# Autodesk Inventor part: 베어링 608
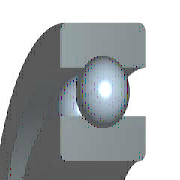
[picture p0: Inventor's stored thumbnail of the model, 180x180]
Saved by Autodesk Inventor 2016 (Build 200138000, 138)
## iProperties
IsCustomPart: 1
Created: 2012-02
Part Number: 베어링 608
Material: 강철, 연강
Description: 깊은 그루브 볼 베어링
Document SubType Name: Modeling
Standard: KS B 2023
Designer: mduedu
Standards Organization: KS
Language: ko-KR
Size Designation: 608 - 8 x 22 x 7
Categories: <MemberInstance><Categories><Category DisplayName="샤프트 부품" InternalName="7f7aeb1f-a693-4053-b835-cee3144e0d98" Mnemonic="SHFT"><Category DisplayName="베어링" Inter
Density: 1 g/cm^3
Appearance: 노란색
Author: mduedu
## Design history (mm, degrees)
sketch "스케치" dims "d0" = 3.64 (= -0.26 x WD + 0.26 x BD)
  geometry: L1 (1.68, 7.5)-(5.32, 7.5); L2 (3.5, 7.5)-(3.5, 5.68); L3 (3.5, 7.5)-(3.5, 9.32); L4 (2.148, 6.282)-(0, 6.282); L5 (0, 4)-(7, 4); L6 (2.148, 8.718)-(0, 8.718); L7 (0, 11)-(7, 11); L8 (7, 4)-(7, 6.282); L9 (4.852, 6.282)-(7, 6.282); L10 (4.852, 8.718)-(7, 8.718); L11 (7, 11)-(7, 8.718); L12 (-1.4, 0)-(8.4, 0) reference; L13 (0, -0.3)-(0, 5.3) reference
  constraints: 22 end point, 4 point on line, 2 collinear, 2 perpendicular, 2 symmetric about line, 1 midpoint, 1 parallel, 14 other
  dimensions: "d9" = 8 diameter of L5 L12 (= WD); "d11" = 22 diameter of L7 L12 (= BD); "d12" = 7 distance between parallel lines of L8 L13 (= KB); "d13" = 12.564 diameter of L9 L12 (= 0.326 x BD + 0.674 x WD)
revolve "본체" stored, may be unused: angle "d6" = 90 deg
revolve "볼" stored, may be unused: angle "d7" = 90 deg
pattern_circular "IDS_ARRAYBALL[SIMPL:T]" dims angle "d3" = 360 deg
body "Solid1"
fillet "모깎기1" dims "d1" = 0.3 (= KRS)
other parameters: "WD" = 8 [user parameter; used in 5 equation terms], "BD" = 22 [user parameter; used in 5 equation terms], "KB" = 7 [user parameter; used in 1 equation term], "KRS" = 0.3 [user parameter; used in 1 equation term], "d4" = 0, "d5" = 0, "d8" = 0, "d14" = 0, "d15" = 0, "BBA" = 0 [user parameter], "BC0" = 1370000 [user parameter], "BC" = 3250000 [user parameter], "BR" = 11 (= 0.5 x BD) [user parameter], "WR" = 4 (= 0.5 x WD) [user parameter]
